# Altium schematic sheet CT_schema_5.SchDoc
size 254 x 245 mm
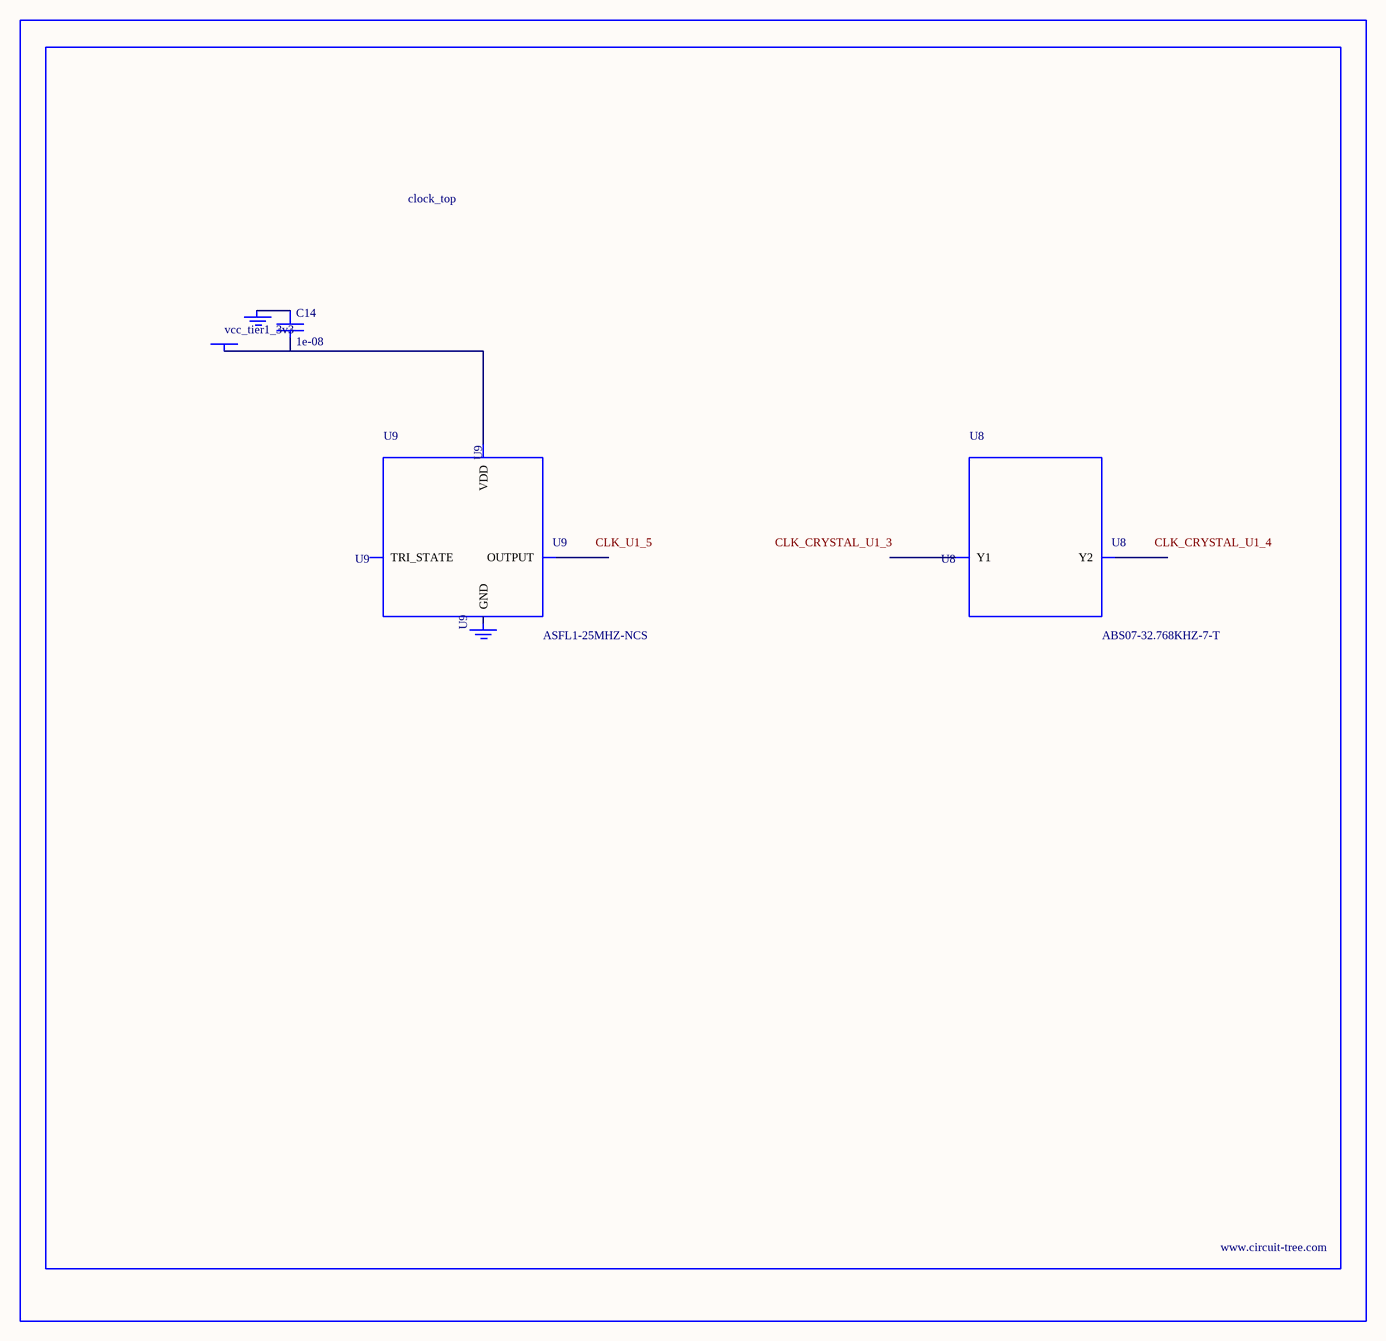
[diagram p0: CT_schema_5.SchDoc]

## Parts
BORDER4  (no value)
C14  1e-08  [C0402]
GND_INSTANCE_4_0  (no value)
GND_INSTANCE_4_1  (no value)
POWER_INSTANCE_4_0  vcc_tier1_3v3
U8  ABS07-32.768KHZ-7-T  [ABS07-32.768KHZ-7-T]
U9  ASFL1-25MHZ-NCS  [ASFL1]

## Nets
NetC14_1: C14.1 GND_INSTANCE_4_0.0(GND)
NetC14_2: C14.2 POWER_INSTANCE_4_0.0(PWR) U9.4(VDD)

Not connected (* = marked no-connect by the designer): GND_INSTANCE_4_1 0(GND); U8 1(Y1) 2(Y2); U9 1(TRI_STATE) 2(GND) 3(OUTPUT)

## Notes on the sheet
- Labels drawn without touching a wire or pin: CLK_CRYSTAL_U1_3, CLK_CRYSTAL_U1_4, CLK_U1_5

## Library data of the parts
BORDER4 = BORDER_PAGE4
C14 = C0402C103K3RAC
GND_INSTANCE_4_0 GND_INSTANCE_4_1 = GND
POWER_INSTANCE_4_0 = PWR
